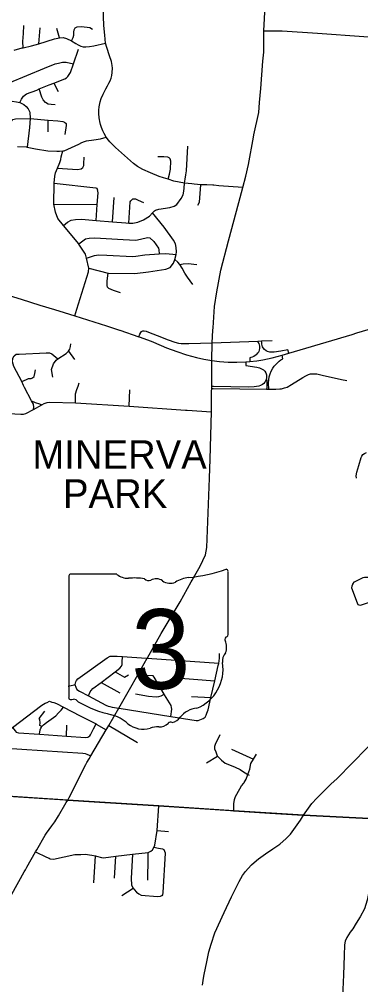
# Model space of a CAD drawing. Extents: x 1755200 to 1902939, y 644115 to 788070.
# Drawn here: x 1845211 to 1851175, y 746938 to 763803 of the extents above; entities that cross this region are included whole.
import ezdxf

# ---------------------------------------------------------------- set-up
doc = ezdxf.new("R2010")
doc.units = 0
for name, color, linetype in [('GM_X_City_Street', 7, 'Continuous'), ('GM_X_Corporation_Text', 7, 'Continuous'), ('GM_X_County_Road', 7, 'Continuous'), ('GM_X_Interchange_Ramps', 7, 'Continuous'), ('GM_X_State_Route', 7, 'Continuous'), ('GM_X_State_Shield', 7, 'Continuous'), ('GM_X_Township', 7, 'Continuous')]:
    doc.layers.add(name, color=color, linetype=linetype)

msp = doc.modelspace()

# ---------------------------------------------------------------- linework, layer by layer
at = {"layer": 'GM_X_City_Street'}
for points in [[(1846771, 761689), (1846729, 761745), (1846693, 761806), (1846671, 761856), (1846658, 761883), (1846647, 761912), (1846630, 761965), (1846618, 762015), (1846609, 762052), (1846605, 762083), (1846600, 762155), (1846600, 762217), (1846604, 762273), (1846624, 762362), (1846642, 762421), (1846674, 762497), (1846723, 762588), (1846752, 762639), (1846775, 762685), (1846796, 762728), (1846814, 762773), (1846826, 762822), (1846835, 762874), (1846837, 762950), (1846834, 762996), (1846821, 763065), (1846788, 763165), (1846739, 763309), (1846716, 763387), (1846702, 763524), (1846685, 763696), (1846672, 764177)], [(1845279, 763305), (1845270, 763412), (1845282, 763556), (1845287, 763696)], [(1845552, 763374), (1845577, 763655)], [(1845911, 763481), (1845866, 763643)], [(1846121, 763429), (1846152, 763485), (1846162, 763526), (1846162, 763576), (1846169, 763621), (1846187, 763654), (1846220, 763673), (1846299, 763677), (1846443, 763659), (1846487, 763632)], [(1845121, 763266), (1845262, 763302), (1845279, 763305), (1845425, 763337), (1845552, 763374), (1845824, 763462), (1845911, 763481), (1845977, 763483), (1846036, 763469), (1846121, 763429), (1846199, 763378), (1846238, 763355), (1846284, 763335), (1846329, 763323), (1846372, 763320), (1846436, 763326), (1846510, 763339), (1846716, 763387)], [(1845217, 762348), (1845246, 762409), (1845281, 762459), (1845336, 762498), (1845514, 762567), (1845559, 762586), (1845734, 762657), (1845813, 762689), (1846007, 762763), (1846037, 762780), (1846061, 762802), (1846103, 762873), (1846155, 763022), (1846246, 763283)], [(1844910, 762390), (1844935, 762529), (1844951, 762621), (1844976, 762655), (1845032, 762694), (1845651, 762950), (1845837, 763024), (1845893, 763039), (1845966, 763052), (1846028, 763051), (1846155, 763022)], [(1843386, 762801), (1843404, 762730), (1843442, 762605), (1843477, 762536), (1843506, 762503), (1843532, 762481), (1843590, 762464), (1843712, 762458), (1844214, 762432), (1844610, 762409), (1844910, 762390), (1845009, 762384), (1845085, 762374), (1845159, 762363), (1845217, 762348), (1845287, 762317), (1845328, 762282), (1845366, 762239), (1845395, 762179), (1845402, 762069), (1845390, 761914), (1845345, 761571)], [(1845813, 762689), (1845888, 762544)], [(1845836, 762309), (1845766, 762316), (1845716, 762323), (1845666, 762348), (1845627, 762397), (1845602, 762445), (1845559, 762586)], [(1845046, 761894), (1845062, 761988), (1845077, 762026), (1845099, 762053), (1845144, 762062), (1845402, 762069)], [(1845402, 762069), (1845713, 762043), (1845883, 762029), (1845969, 762017), (1846001, 762007), (1846029, 761980), (1846028, 761948), (1846006, 761790)], [(1845713, 761836), (1845713, 762043)], [(1845177, 761583), (1845330, 761574), (1845345, 761571), (1845494, 761541), (1845708, 761507), (1845868, 761498), (1845910, 761499), (1845973, 761504), (1845993, 761506), (1846251, 761624), (1846304, 761650), (1846348, 761667), (1846383, 761678), (1846515, 761696), (1846631, 761713), (1846729, 761745)], [(1848098, 760942), (1848106, 761010), (1848122, 761083), (1848132, 761154), (1848155, 761585)], [(1846179, 758622), (1846216, 758737), (1846419, 759390), (1846427, 759457), (1846385, 759631), (1846369, 759698), (1846253, 759874), (1846248, 759880), (1845983, 760203), (1845885, 760322), (1845840, 760436), (1845813, 760574), (1845819, 760938), (1845831, 761061), (1845845, 761119), (1845878, 761204), (1845920, 761302), (1845936, 761354), (1845944, 761402), (1845973, 761504)], [(1845878, 761204), (1846230, 761181), (1846292, 761191), (1846318, 761214), (1846336, 761248), (1846338, 761278), (1846343, 761392)], [(1847809, 761008), (1847837, 761100), (1847850, 761184), (1847856, 761322), (1847846, 761367), (1847829, 761381), (1847805, 761392), (1847735, 761400), (1847630, 761402)], [(1845819, 760938), (1846545, 760860), (1846561, 760850), (1846575, 760828)], [(1845983, 760203), (1846050, 760260), (1846116, 760295), (1846193, 760307), (1846299, 760310), (1846552, 760288), (1846838, 760264), (1847069, 760245), (1847125, 760243), (1847195, 760242), (1847284, 760258), (1847380, 760297), (1847484, 760365), (1847537, 760419), (1847572, 760454), (1847592, 760468), (1847650, 760488), (1847839, 760515), (1847917, 760540), (1847963, 760568), (1848038, 760670), (1848071, 760735), (1848087, 760798), (1848092, 760854), (1848098, 760942)], [(1848590, 760905), (1848485, 760912), (1848384, 760913), (1848265, 760925), (1848222, 760930)], [(1848332, 760557), (1848357, 760610), (1848384, 760913)], [(1846552, 760288), (1846572, 760570), (1846586, 760772), (1846575, 760828)], [(1849115, 760862), (1848695, 760896)], [(1845813, 760574), (1846572, 760570)], [(1846838, 760264), (1846867, 760691)], [(1847125, 760243), (1847147, 760614), (1847161, 760634), (1847195, 760667), (1847241, 760665), (1847290, 760645), (1847378, 760605)], [(1847906, 759946), (1847744, 760174), (1847537, 760419)], [(1846248, 759880), (1846365, 759969), (1846431, 759981), (1846528, 759988), (1847024, 759958), (1847245, 759943), (1847325, 759962), (1847452, 759992), (1847490, 759986), (1847561, 759919), (1847640, 759805), (1847650, 759775), (1847656, 759708)], [(1846427, 759457), (1846761, 759370), (1847226, 759362), (1847469, 759393), (1847770, 759437), (1847844, 759469), (1847904, 759543), (1847930, 759607), (1847951, 759695), (1847955, 759738), (1847949, 759816), (1847940, 759880), (1847906, 759946)], [(1846385, 759631), (1846525, 759677), (1846594, 759686), (1846738, 759682), (1847188, 759658), (1847247, 759667), (1847401, 759691), (1847656, 759708), (1847771, 759711), (1847951, 759695)], [(1848244, 759172), (1848149, 759300), (1848104, 759368), (1848055, 759458), (1848017, 759518), (1847980, 759562), (1847930, 759607)], [(1848017, 759518), (1848073, 759532), (1848163, 759537), (1848312, 759519)], [(1846979, 759026), (1846854, 759063), (1846776, 759099), (1846751, 759123), (1846745, 759155), (1846745, 759233), (1846761, 759370)], [(1847296, 758256), (1847318, 758300), (1847332, 758332), (1847347, 758349), (1847370, 758360), (1847392, 758362), (1847427, 758353), (1847469, 758338), (1847621, 758277), (1847809, 758205), (1847927, 758160), (1847991, 758145), (1848038, 758139), (1848175, 758140), (1848374, 758143), (1848582, 758151), (1849375, 758179), (1849444, 758183), (1849628, 758189)], [(1845799, 757551), (1845775, 757683), (1845807, 757783), (1845856, 757851), (1845884, 757871), (1846027, 757962), (1846069, 758003), (1846091, 758038), (1846107, 758087), (1846111, 758131)], [(1845286, 757408), (1845254, 757473), (1845117, 757735), (1845093, 757821), (1845100, 757881), (1845122, 757923)], [(1845122, 757923), (1845154, 757953), (1845211, 757954), (1845677, 757976), (1845738, 757974), (1845778, 757956), (1845884, 757871)], [(1846069, 758003), (1846175, 757862)], [(1845254, 757473), (1845335, 757512), (1845373, 757525), (1845415, 757525), (1845443, 757537), (1845470, 757561), (1845480, 757613), (1845493, 757681)], [(1849567, 757342), (1849693, 757343), (1849761, 757347), (1849792, 757350), (1849842, 757362), (1849890, 757379), (1849968, 757425), (1850164, 757544), (1850214, 757573), (1850261, 757595), (1850298, 757608), (1850346, 757611), (1850406, 757607), (1850501, 757585), (1850841, 757512), (1850933, 757491)], [(1845458, 756989), (1845463, 757027), (1845461, 757079), (1845425, 757137), (1845304, 757372), (1845286, 757408)], [(1846195, 757224), (1846195, 757225), (1846195, 757262), (1846218, 757338), (1846240, 757392), (1846255, 757454)], [(1846192, 757104), (1846195, 757224)], [(1847132, 757043), (1847140, 757331)], [(1844381, 756949), (1845236, 756903), (1845284, 756902), (1845327, 756918), (1845458, 756989), (1845607, 757070), (1845642, 757089), (1845695, 757106), (1845743, 757117), (1846192, 757104), (1847132, 757043), (1848116, 756977), (1848145, 756975)], [(1845425, 757137), (1845489, 757110), (1845563, 757084), (1845607, 757070)], [(1848145, 756975), (1848566, 756944)], [(1851102, 755787), (1851097, 755828), (1851107, 755890), (1851142, 756007), (1851185, 756149), (1851197, 756174), (1851212, 756198), (1851240, 756218), (1851276, 756235)], [(1851037, 753940), (1851069, 753975), (1851092, 753990), (1851196, 754040), (1851218, 754052), (1851239, 754059), (1851416, 754060), (1851430, 754060), (1851450, 754060), (1851512, 754061), (1851552, 754051), (1851639, 754002), (1851657, 753982), (1851676, 753919)], [(1851037, 753940), (1851020, 753898), (1851016, 753870), (1851115, 753608), (1851127, 753582), (1851141, 753574), (1851169, 753568), (1851725, 753751)], [(1846170, 752177), (1846183, 752180), (1846189, 752182), (1846193, 752208), (1846199, 752228), (1846209, 752252), (1846234, 752281), (1846743, 752651), (1846797, 752675)], [(1846418, 751984), (1846447, 752053), (1846466, 752075), (1846498, 752112), (1846641, 752220), (1846887, 752406), (1846967, 752467), (1846996, 752502), (1847006, 752534), (1847010, 752570), (1847016, 752671)], [(1846797, 752675), (1846826, 752678), (1846865, 752680), (1846921, 752677), (1847016, 752671), (1847428, 752642), (1847430, 752642)], [(1848422, 751591), (1848459, 751610), (1848475, 751644), (1848489, 751682), (1848508, 751738), (1848558, 751955), (1848626, 752249), (1848687, 752516), (1848694, 752548), (1848695, 752553), (1848704, 752592), (1848709, 752648), (1848707, 752726)], [(1847430, 752642), (1847447, 752641), (1848695, 752553)], [(1846887, 752406), (1847050, 752311), (1847118, 752351)], [(1847749, 752004), (1847742, 752016), (1847568, 752310), (1847550, 752333), (1847416, 752342)], [(1846063, 752155), (1846168, 752177), (1846170, 752177)], [(1846183, 752180), (1846196, 752137), (1846218, 752097), (1846260, 752067), (1846418, 751984), (1846723, 751824), (1846765, 751805), (1846795, 751797), (1846835, 751788), (1846949, 751770), (1846956, 751769)], [(1846641, 752220), (1846969, 752034)], [(1847882, 752305), (1848626, 752249)], [(1847243, 752017), (1847468, 751979), (1847602, 751965), (1847646, 751971), (1847690, 751986), (1847742, 752016)], [(1847859, 751623), (1847878, 751752), (1847870, 751778), (1847861, 751814), (1847750, 752002), (1847749, 752004)], [(1848216, 751973), (1848558, 751955)], [(1844586, 751052), (1844746, 751172), (1845089, 751430), (1845606, 751820), (1845661, 751859), (1845698, 751868), (1845736, 751889)], [(1845736, 751889), (1845778, 751874), (1845816, 751867), (1845861, 751848), (1845981, 751786), (1846271, 751635), (1846552, 751493), (1846556, 751491), (1846729, 751388)], [(1845555, 751589), (1845656, 751715)], [(1845561, 751314), (1845575, 751391), (1845587, 751419), (1845604, 751448), (1845635, 751478), (1845688, 751521), (1845849, 751636), (1845896, 751689), (1845939, 751732), (1845981, 751786)], [(1846956, 751769), (1846956, 751769), (1847859, 751623), (1848300, 751552), (1848336, 751555), (1848366, 751565), (1848422, 751591)], [(1845089, 751430), (1845139, 751371), (1845154, 751352), (1845198, 751339), (1845561, 751314), (1846033, 751280), (1846369, 751256), (1846409, 751265), (1846442, 751287), (1846454, 751302), (1846504, 751406), (1846552, 751493)], [(1845604, 751448), (1845568, 751469), (1845574, 751513), (1845568, 751570), (1845555, 751589)], [(1846033, 751280), (1846039, 751470)], [(1846773, 751465), (1847275, 751171)], [(1848675, 750929), (1848647, 751001), (1848626, 751051), (1848627, 751108), (1848636, 751140), (1848719, 751309)], [(1844746, 751172), (1844781, 751116), (1844811, 751099), (1844835, 751093), (1844898, 751077), (1846323, 750980), (1846361, 750976), (1846391, 750965), (1846460, 750934)], [(1848918, 751053), (1849302, 750879)], [(1849139, 750472), (1849172, 750531), (1849204, 750613), (1849238, 750701), (1849255, 750800), (1849302, 750879), (1849353, 750964)], [(1848482, 750812), (1848675, 750929)], [(1848675, 750929), (1848742, 750861), (1848806, 750808), (1848884, 750778), (1848982, 750739), (1849067, 750695), (1849111, 750669), (1849204, 750613), (1849228, 750598)], [(1841691, 750460), (1842732, 750381), (1843414, 750335), (1844025, 750293), (1846006, 750167)], [(1848956, 749976), (1848961, 750100), (1848969, 750171), (1848986, 750226), (1849011, 750269), (1849093, 750411), (1849131, 750458), (1849139, 750472)], [(1850178, 749898), (1850324, 750103), (1850408, 750195), (1850488, 750277), (1850588, 750376)], [(1846006, 750167), (1846056, 750164), (1846427, 750141)], [(1846427, 750141), (1847649, 750064), (1848900, 749980)], [(1847459, 749250), (1847507, 749271), (1847540, 749295), (1847562, 749337), (1847578, 749374), (1847617, 749632), (1847649, 750064)], [(1848900, 749980), (1848953, 749977)], [(1848953, 749977), (1848956, 749976), (1849585, 749936)], [(1848441, 747114), (1848484, 747338), (1848524, 747512), (1848562, 747647), (1848628, 747845), (1848787, 748202), (1848917, 748476), (1849003, 748646), (1849050, 748739), (1849112, 748844), (1849162, 748916), (1849207, 748970), (1849269, 749035), (1849313, 749075), (1849390, 749136), (1849511, 749223), (1849637, 749311), (1849760, 749396), (1849870, 749490), (1849948, 749568), (1850121, 749810), (1850178, 749898)], [(1849585, 749936), (1850164, 749899)], [(1850164, 749899), (1850178, 749898), (1851432, 749838), (1853581, 749702), (1854164, 749653), (1854211, 749651)], [(1851432, 749838), (1851405, 749428), (1851356, 749164), (1851343, 748864), (1851333, 748672), (1851315, 748559), (1851290, 748415), (1851241, 748265), (1851165, 748123), (1851097, 748013), (1851039, 747917), (1850993, 747855), (1850933, 747761), (1850903, 747696), (1850893, 747632), (1850888, 747450), (1850873, 747113), (1850864, 746855), (1850853, 746374), (1850846, 746224), (1850838, 745952), (1850846, 745706), (1850886, 745480), (1850900, 745441)], [(1847617, 749632), (1847818, 749617)], [(1847707, 748491), (1847717, 748511), (1847724, 748551), (1847765, 749234), (1847755, 749268), (1847742, 749292), (1847718, 749305), (1847678, 749314), (1847640, 749317), (1847562, 749337)], [(1845495, 749259), (1845688, 749168), (1845730, 749147), (1845752, 749135), (1845806, 749130), (1846183, 749212), (1846284, 749215), (1846364, 749216), (1846477, 749201), (1846539, 749188), (1846559, 749184), (1846649, 749162), (1846682, 749157), (1846895, 749182), (1847191, 749218), (1847459, 749250)], [(1846513, 748719), (1846539, 749188)], [(1846875, 748802), (1846895, 749182)], [(1847191, 749218), (1847163, 748792), (1847173, 748685), (1847196, 748633), (1847202, 748624), (1847217, 748604), (1847258, 748557), (1847299, 748524), (1847337, 748501), (1847623, 748481), (1847675, 748486), (1847699, 748494), (1847707, 748491)], [(1847457, 748763), (1847463, 749152), (1847463, 749182), (1847464, 749222), (1847459, 749250)], [(1847003, 748499), (1847202, 748624)], [(1848412, 746932), (1848425, 747012), (1848436, 747085), (1848441, 747114)]]:
    msp.add_lwpolyline(points, dxfattribs=at)
at = {"layer": 'GM_X_County_Road'}
for points in [[(1849485, 763600), (1849753, 763601), (1849804, 763601), (1850422, 763559), (1851230, 763501), (1852094, 763449), (1852383, 763425), (1852787, 763400), (1853135, 763377)], [(1848222, 760930), (1848098, 760942), (1847910, 760976), (1847809, 761008), (1847729, 761031), (1847655, 761057), (1847502, 761118), (1847369, 761181), (1847273, 761229), (1847207, 761282), (1846892, 761564), (1846790, 761665), (1846771, 761689)], [(1848695, 760896), (1848608, 760903), (1848590, 760905)], [(1850625, 750413), (1850654, 750442), (1850761, 750538), (1851287, 751075), (1851650, 751428), (1851672, 751448)], [(1850588, 750376), (1850591, 750379), (1850625, 750413)]]:
    msp.add_lwpolyline(points, dxfattribs=at)
at = {"layer": 'GM_X_Interchange_Ramps'}
for points in [[(1849375, 758179), (1849376, 758161), (1849393, 758141), (1849403, 758118), (1849407, 758092), (1849406, 758059), (1849402, 758025), (1849393, 757999), (1849381, 757977), (1849368, 757962), (1849351, 757943), (1849331, 757928), (1849306, 757911), (1849279, 757898), (1849258, 757892), (1849237, 757889), (1849240, 757827)], [(1849922, 757968), (1849904, 758030), (1849778, 758006), (1849661, 757989), (1849625, 757987), (1849590, 757990), (1849546, 757999), (1849524, 758014), (1849494, 758035), (1849471, 758061), (1849461, 758083), (1849446, 758126), (1849445, 758158), (1849444, 758183)], [(1848572, 757354), (1848598, 757354), (1849531, 757341), (1849567, 757342), (1849566, 757446), (1849568, 757506), (1849576, 757557), (1849592, 757609), (1849611, 757657), (1849640, 757710), (1849664, 757742), (1849684, 757768), (1849713, 757798), (1849748, 757828), (1849781, 757854), (1849817, 757874), (1849800, 757934)], [(1849166, 757820), (1849168, 757754), (1849359, 757725), (1849407, 757714), (1849442, 757699), (1849474, 757680), (1849498, 757654), (1849516, 757626), (1849528, 757589), (1849531, 757546), (1849523, 757507), (1849513, 757488), (1849500, 757464), (1849482, 757442), (1849459, 757423), (1849425, 757405), (1849393, 757394), (1849312, 757382), (1849209, 757378), (1848603, 757389), (1848572, 757390)], [(1849523, 757507), (1849535, 757505), (1849533, 757371), (1849531, 757341)]]:
    msp.add_lwpolyline(points, dxfattribs=at)
at = {"layer": 'GM_X_State_Route'}
for points in [[(1849309, 761782), (1849394, 762176), (1849408, 762349), (1849429, 762591), (1849464, 763073), (1849480, 763231), (1849485, 763600), (1849506, 764034)], [(1849166, 761065), (1849216, 761265), (1849301, 761745), (1849309, 761782)], [(1849046, 760605), (1849115, 760862), (1849166, 761065)], [(1848593, 758372), (1848595, 758411), (1848622, 758787), (1848660, 759040), (1848732, 759419), (1848866, 759935), (1849046, 760605)], [(1842790, 759605), (1842822, 759597), (1843184, 759501), (1843848, 759328), (1844230, 759224), (1845241, 758914), (1845570, 758811)], [(1845570, 758811), (1845826, 758732)], [(1845826, 758732), (1845992, 758681), (1846179, 758622), (1846732, 758450), (1846961, 758372), (1846965, 758371), (1847296, 758256), (1847303, 758253)], [(1851109, 758323), (1851504, 758442)], [(1847303, 758253), (1847512, 758180), (1847555, 758162)], [(1848573, 757785), (1848574, 757841), (1848582, 758151), (1848593, 758372)], [(1850120, 758028), (1851023, 758298), (1851109, 758323)], [(1847555, 758162), (1847785, 758066), (1847964, 757997), (1848133, 757940), (1848304, 757893), (1848433, 757865), (1848574, 757841)], [(1848574, 757841), (1848707, 757826), (1848861, 757815), (1849013, 757814), (1849166, 757820), (1849240, 757827), (1849360, 757838), (1849466, 757855), (1849631, 757890), (1849800, 757934), (1849922, 757968), (1850120, 758028)], [(1848571, 757303), (1848572, 757354), (1848572, 757390), (1848572, 757583), (1848573, 757785)], [(1848566, 756944), (1848571, 757303)], [(1848534, 755787), (1848546, 756119), (1848566, 756944)], [(1848233, 754007), (1848369, 754250), (1848464, 754446), (1848487, 754574), (1848534, 755787)], [(1846393, 750819), (1846431, 750885), (1846460, 750934), (1846729, 751388), (1846741, 751409), (1846773, 751465), (1846949, 751770), (1847183, 752178), (1847447, 752641), (1847451, 752648), (1847688, 753073), (1848018, 753625), (1848215, 753976), (1848233, 754007)], [(1846080, 750211), (1846373, 750785), (1846393, 750819)], [(1845896, 749891), (1846030, 750119)], [(1846030, 750119), (1846056, 750164)], [(1846056, 750164), (1846080, 750211)], [(1845781, 749714), (1845834, 749786), (1845896, 749891)], [(1845688, 749586), (1845781, 749714)], [(1845344, 748992), (1845495, 749259), (1845516, 749296), (1845662, 749552), (1845688, 749586)], [(1844359, 747245), (1844741, 747937), (1844771, 747992), (1845079, 748521), (1845298, 748910), (1845319, 748946)], [(1845319, 748946), (1845344, 748992)]]:
    msp.add_lwpolyline(points, dxfattribs=at)
at = {"layer": 'GM_X_State_Shield'}
for p, q in [((1846073, 754070), (1846073, 751957)), ((1846915, 754107), (1846100, 754107)), ((1848857, 753053), (1848857, 754159)), ((1848857, 753054), (1848857, 753053))]:
    msp.add_line(p, q, dxfattribs=at)
for centre, radius, start, end in [((1847865, 756988), 2953, 275.8445, 288.9065), ((1848826, 754164), 31, 351.8621, 97.738), ((1846105, 754075), 32.3, 98.1301, 188.1301), ((1847110, 754352), 313, 231.6195, 271.1119), ((1847213, 752920), 1123, 80.4867, 94.9883), ((1847468, 754086), 90.3, 219.7921, 297.1024), ((1847601, 753841), 188, 54.4667, 119.1411), ((1848242, 753461), 594, 97.3462, 120.7689), ((1847843, 754176), 226, 233.8562, 294.8282), ((1848850, 752972), 48, 107.944, 210.337), ((1848824, 753049), 33.2, 289.6038, 7.7341), ((1848545, 752833), 288, 340.033, 23.6496), ((1848968, 752591), 210, 136.8065, 186.9296), ((1848031, 752450), 739, 292.3089, 8.9858), ((1846105, 751952), 32.5, 171.9584, 258.3066), ((1846110, 752169), 248, 267.339, 280.6039), ((1846161, 751835), 89.5, 29.7484, 93.2717), ((1847291, 753734), 2132, 240.4129, 257.1985), ((1846655, 751008), 667, 47.1842, 75.836), ((1848342, 751364), 404, 94.4031, 142.5768), ((1847377, 751825), 423, 230.7004, 286.2918), ((1847653, 751666), 226, 268.777, 315.5493), ((1847857, 751462), 63.5, 65.7517, 132.6484), ((1847830, 751752), 239, 282.8732, 323.2771), ((1847622, 751094), 348, 85.6951, 111.2099)]:
    msp.add_arc(centre, radius, start, end, dxfattribs=at)
at = {"layer": 'GM_X_Township'}
msp.add_lwpolyline([(1863172, 749017), (1862472, 749064), (1862160, 749085), (1861567, 749127), (1860368, 749204), (1859239, 749292), (1857164, 749442), (1856152, 749530), (1855788, 749550), (1855559, 749563), (1855330, 749578), (1854995, 749599), (1854678, 749625), (1854164, 749653), (1853581, 749702), (1851432, 749838), (1850178, 749898), (1848956, 749976), (1847649, 750064), (1846056, 750164), (1844025, 750293)], dxfattribs=at)

# ---------------------------------------------------------------- texts
at = {"layer": 'GM_X_Corporation_Text'}
for s, p in [('MINERVA', (1845439, 755950)), ('PARK', (1845974, 755268))]:
    msp.add_text(s, height=500, rotation=0, dxfattribs=at).set_placement(p)
at = {"layer": 'GM_X_State_Shield'}
msp.add_text('3', height=1392, dxfattribs=at).set_placement((1847164, 752106))

doc.saveas('drawing.dxf')
